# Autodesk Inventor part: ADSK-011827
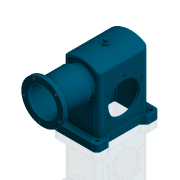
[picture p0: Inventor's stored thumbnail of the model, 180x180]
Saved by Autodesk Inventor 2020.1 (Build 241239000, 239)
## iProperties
Created: 2000-02
Part Number: ADSK-011827
Material: RA HRS
Document SubType Name: Modeling
Designer: glanglot
Density: 7.83 g/cm^3
Appearance: Bearing Blue
Mass: 18740 g
Surface Area: 5032.13 cm^2
Volume: 2393.35 cm^3
Control State: 0
Master: False
Checked Out: False
Shininess: 20.0
Length Units: 11269
Angle Units: 11279
Time Units: 11290
Mass Units: 11283
Length Display Precision: 3
Angle Display Precision: 2
Compacted: True
Dimensions: 178x291x377 mm
Mass: 18,74 kg
DocNumber: ADSK-011827_1.ipt
Folder: 01 - Themengebiete\Simplification\01 - Packaging machine\
VDS_Category: 3D Komponenten
VDS_NumSchm: Kein
Density: 0.0
Volumn: 0.0
Area: 0.0
PropertySet Name: Model Information
Title: A105195
Author: glanglot
Revision Number: -
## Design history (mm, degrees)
workaxis "Arbeitsachse3"
node "Extrusion1" dims "d2" = 0, "shaft_length_front" = 170
  sketch "Sketch1"
    geometry: C1 r 12.5 at (0, 0); 1 further point
    constraints: 1 centre point, 1 coincident
    dimensions: "d0" = 25 diameter of C1
sketch "Sketch2"
  geometry: L1 (-70, 76)-(70, 76); L2 (70, 76)-(70, -169); L3 (-70, -169)-(-70, 76); L4 (-70, -60.325)-(70, -60.325); L5 (-70, 52)-(70, 52); L6 (-89, -197)-(89, -197); L7 (89, -197)-(89, -169); L8 (89, -169)-(-89, -169); L9 (-89, -169)-(-89, -197); L10 (0, 76)-(0, -197); A1 r 114.083 centre (0, -38.083) between (70, 52) and (-70, 52); 1 further point
  constraints: 20 end point, 7 point on line, 4 parallel, 3 point on circle, 2 horizontal, 2 midpoint, 2 perpendicular, 1 centre point, 1 vertical
  dimensions: "d3" = 76 distance from line of point (0, 0) L1; "d6" = 140 distance between parallel lines of L2 L3; "d7" = 24 distance between parallel lines of L5 L1; "d8" = 178 distance between parallel lines of L7 L9; "d9" = 28 distance between parallel lines of L8 L6; "d10" = 197 distance from line of point (0, 0) L6
node "Extrusion2" dims "d11" = 200, "d12" = 0
node "Extrusion3" dims "d13" = 250, "d14" = 0
workaxis "Arbeitsachse4"
  workplane "Arbeitsebene8"
node "Extrusion4" dims "d18" = 0, "shaft_length_right_left" = 300
  sketch "Sketch3"
    geometry: L1 (-197, -125)-(-197, 125) reference; L2 (-197, 0)-(-77, 0); C1 r 19 at (-77, 0)
    constraints: 2 end point, 1 centre point, 1 coincident, 1 midpoint, 1 perpendicular
    dimensions: "d15" = 38 diameter of C1
node "Extrusion5" dims "d20" = 10, "d21" = 0
  sketch "Sketch4"
    geometry: C1 r 56.5 at (0, 0); C2 r 12.5 at (0, 0); 1 further point
    constraints: 2 centre point, 2 coincident
    dimensions: "d19" = 113 diameter of C1; "d199" = 25 diameter of C2
node "Extrusion6" dims "d37" = 7.493, "d38" = 0
  sketch "Sketch5"
    geometry: L1 (-124.6, 0)-(124.6, 0) reference; L2 (45, -15.911)-(45, 0); L3 (45, 0)-(58.557, -23.481); L4 (45, 0)-(34.815, -17.64); L5 (45, 0)-(16.133, 0); L6 (45, 0)-(76.079, 0); L7 (45, 0)-(29.151, 27.452); L8 (45, 0)-(45, 29.465); L9 (45, 0)-(64.626, 33.993); L10 (49.041, -7)-(40.959, -7); L11 (49.041, -7)-(53.083, 0); L12 (40.959, -7)-(36.917, 0); L13 (36.917, 0)-(40.959, 7); L14 (40.959, 7)-(49.041, 7); L15 (53.083, 0)-(49.041, 7); C1 r 12.5 at (0, 0) reference; 1 further point
    constraints: 28 end point, 7 point on line, 4 perpendicular, 3 collinear, 3 parallel, 1 coincident, 1 equal length, 3 other
    dimensions: "d33" = 7 distance between parallel lines of L10 L6; "d34" = 30 deg angle of L8 L7; "d35" = 30 deg angle of L9 L8 (= d34); "d36" = 45 distance of L2.end C1.centre
node "Circular Pattern1" dims "d39" = 60, "d41" = 60 deg
node "Extrusion7" dims "d43" = 9.525, "d44" = 0
  sketch "Sketch6"
    geometry: C1 r 88.9 at (100, -129); C2 r 19 at (100, -129)
    constraints: 2 centre point, 1 coincident
    dimensions: "d42" = 177.8 diameter of C1; "d197" = 38 diameter of C2
node "Extrusion8" dims "d49" = 7.493, "d50" = 0
  sketch "Sketch7"
    geometry: L1 (0, 0)-(202.768, 0); L2 (76, 0)-(76, 13.354); L3 (76, 0)-(67.315, 15.042); L4 (76, 0)-(81.961, 10.326); L5 (71.959, 7)-(80.041, 7); L6 (80.041, 7)-(84.083, 0); L7 (71.959, 7)-(67.917, 0); L8 (67.917, 0)-(71.959, -7); L9 (71.959, -7)-(80.041, -7); L10 (80.041, -7)-(84.083, 0); C1 r 88.9 at (0, 0) reference
    constraints: 20 end point, 5 parallel, 5 point on line, 2 equal length, 1 coincident, 1 horizontal, 1 perpendicular
    dimensions: "d45" = 7 distance between parallel lines of L1 L5; "d46" = 30 deg angle of L2 L3; "d47" = 30 deg angle of L4 L2; "d48" = 76 distance of L2.start L1.start
node "Circular Pattern2" dims "d51" = 60, "d53" = 60 deg
workplane "Work Plane3"
node "Extrusion12" dims "d70" = 5, "d71" = 0
  sketch "Sketch11"
    geometry: L1 (100, -5)-(150, -5); L2 (100, 5)-(150, 5); L3 (150, -5)-(150, 5); L4 (0, -7)-(0, 7) reference; L5 (197.8, 0)-(-136.8, 0) reference; A1 r 5 centre (100, 0) between (100, -5) and (100, 5); 1 further point
    constraints: 6 end point, 2 horizontal, 2 point on circle, 2 tangent, 1 centre point, 1 midpoint, 1 point on line, 1 vertical
    dimensions: "d68" = 10 diameter of A1; "d200" = 150 distance between parallel lines of L3 L4 (derived); "d201" = 50 distance of L1.start L1.end
node "Extrusion15" dims "d135" = 5, "d136" = 0
  sketch "Sketch18"
    geometry: L1 (-100, 5)-(-150, 5); L2 (-100, -5)-(-150, -5); L3 (-150, -5)-(-150, 5); L4 (136.8, 0)-(-197.8, 0) reference; L5 (0, -7)-(0, 7) reference; A1 r 5 centre (-100, 0) between (-100, 5) and (-100, -5); 1 further point
    constraints: 6 end point, 2 point on circle, 2 point on line, 2 tangent, 1 centre point, 1 horizontal, 1 midpoint, 1 vertical
    dimensions: "d133" = 10 diameter of A1; "d202" = 50 distance of L2.start L2.end; "d203" = 150 distance between parallel lines of L3 L5 (derived)
node "Mirror1"
workplane "Work Plane1"
node "Extrusion9" dims "d56" = 6, "d57" = 0
  sketch "Sketch8"
    geometry: C1 r 12.5 at (0, 0); 1 further point
    constraints: 1 centre point, 1 coincident
    dimensions: "d55" = 25 diameter of C1
node "Extrusion10" dims "d60" = 12, "d61" = 0
  sketch "Sketch9"
    geometry: L1 (-6, 6)-(6, 6); L2 (6, 6)-(6, -6); L3 (6, -6)-(-6, -6); L4 (-6, -6)-(-6, 6); L5 (0, 6)-(0, -6); L6 (6, 0)-(-6, 0); C1 r 12.5 at (0, 0) reference
    constraints: 12 end point, 6 midpoint, 2 parallel, 1 horizontal, 1 perpendicular
    dimensions: "d58" = 12 distance between parallel lines of L2 L4; "d59" = 12 distance between parallel lines of L3 L1 (= d58)
workplane "Work Plane2"
node "Extrusion11" dims "d65" = 3.5814, "d66" = 0
  sketch "Sketch10"
    geometry: L1 (3, 125)-(3, 170); L2 (-3, 125)-(-3, 170); L3 (3, 170)-(-3, 170); L4 (0, -184)-(0, 229) reference; L5 (-124.6, 0)-(124.6, 0) reference; A1 r 3 centre (0, 125) between (3, 125) and (-3, 125); 1 further point
    constraints: 6 end point, 2 point on circle, 2 tangent, 2 vertical, 1 centre point, 1 horizontal, 1 midpoint, 1 point on line
    dimensions: "d64" = 6 diameter of A1; "d204" = 170 distance between parallel lines of L5 L3 (derived); "d205" = 45 distance of L2.start L2.end
node "Chamfer1" dims "d137" = 0.8, "d138" = 0.8, "d180" = 45 deg
node "Hole1" dims "d80" = 13.5, "d81" = 9.525, "d82" = 6.35, "d83" = 60 deg, "d84" = 19.05, "d85" = 118 deg, "d198" = 6
  sketch "Sketch12"
    geometry: L1 (17.5, -231.5)-(160.5, -231.5); L2 (160.5, -231.5)-(160.5, -18.5); L3 (160.5, -18.5)-(17.5, -18.5); L4 (17.5, -18.5)-(17.5, -231.5); L5 (0, -250)-(0, 0) reference; L6 (0, -250)-(178, -250) reference; 6 further points
    constraints: 8 end point, 4 midpoint, 2 coincident, 2 parallel, 1 horizontal, 1 horizontal alignment, 1 perpendicular, 1 vertical alignment
    dimensions: "d181" = 143 distance of L2.end L3.end; "d182" = 213 distance of L3.end L1.start
node "Mirror2"
node "Extrusion13" dims "d94" = 25.4, "d95" = 0
  sketch "Sketch14"
    geometry: L1 (19, 224.919)-(19, 25.081) reference; L2 (19.32, 225)-(158.68, 225) reference; L3 (28.678, 225)-(19, 215.322); C1 r 12.5 at (17.5, 231.5); C2 r 12.5 at (160.5, 231.5); C3 r 12.5 at (160.5, 18.5); C4 r 12.5 at (17.5, 18.5); A1 r 6.75 centre (17.5, 18.5) between (19, 25.081) and (19.32, 25) reference; A2 r 6.75 centre (160.5, 231.5) between (159, 224.919) and (158.68, 225) reference; A3 r 6.75 centre (160.5, 18.5) between (158.68, 25) and (159, 25.081) reference; A4 r 16.521 centre (35.521, 208.479) between (35.521, 225) and (19, 208.479); A5 r 6.75 centre (17.5, 231.5) between (19, 224.919) and (19.32, 225) reference
    constraints: 5 centre point, 4 point on line, 4 tangent, 3 coincident, 3 equal radius, 2 end point, 2 point on circle, 1 concentric
    dimensions: "d92" = 45 deg angle of L2 L3; "d96" = 25 diameter of C1
node "Mirror3"
node "Mirror4"
node "Extrusion14" dims "d129" = 28 (= d9), "d130" = 0
  sketch "Sketch17"
    geometry: L1 (0, -250)-(0, 0) reference; L2 (178, -250)-(178, 0) reference; L3 (18, -186.5)-(18, -63.5); L4 (160, -63.5)-(160, -186.5); L5 (160, -63.5)-(178, -45.5); L6 (18, -63.5)-(0, -45.5); L7 (18, -186.5)-(0, -204.5); L8 (160, -186.5)-(178, -204.5); L9 (160, -125)-(18, -125); L10 (89, 50)-(89, -300) reference; 2 further points
    constraints: 14 end point, 5 midpoint, 4 point on line, 3 equal length, 3 horizontal alignment, 1 vertical
    dimensions: "d183" = 18 distance between parallel lines of L1 L3; "d184" = 123 distance of L3.start L3.end; "d185" = 45 deg angle of L1 L7
node "Fillet3" dims "d131" = 17.5
node "Fillet4" dims "d132" = 6
node "Revolution1" dims "d110" = 90 deg
  sketch "Sketch15"
    geometry: L1 (0, 282.4)-(0, 69.6) reference; L2 (84, 252)-(84, 238); L3 (84, 238)-(63.5, 238); L4 (63.5, 238)-(63.5, 125.5); L5 (63.5, 125.5)-(56, 118); L6 (84, 252)-(57, 252); L7 (57.5, 242.887)-(57.5, 144); L8 (55.5, 128)-(0, 128); L9 (-219.6, 0)-(134.6, 0) reference; L10 (57.5, 242.887)-(57, 242.887); L11 (55.5, 128)-(55.5, 139.374); L12 (57, 252)-(57, 242.887); L13 (-169, 100)-(62.689, 100) reference; L14 (56, 118)-(56, 100); L15 (56, 100)-(0, 100); L16 (0, 100)-(0, 128); A1 r 6.35 centre (51.15, 144) between (55.5, 139.374) and (57.5, 144); 1 further point
    constraints: 26 end point, 6 perpendicular, 6 point on line, 2 parallel, 2 point on circle, 1 centre point, 1 tangent, 1 vertical
    dimensions: "d97" = 84 distance between parallel lines of L1 L2; "d98" = 63.5 distance between parallel lines of L1 L4; "d101" = 14 distance between parallel lines of L3 L6; "d104" = 242.8875 distance between parallel lines of L9 L10; "d105" = 12.7 diameter of A1; "d106" = 6 distance between parallel lines of L4 L7; "d107" = 55.5 distance between parallel lines of L1 L11; "d108" = 16 distance from line of A1.centre L8; "d109" = 57 distance between parallel lines of L12 L1; "d188" = 56 distance between parallel lines of L1 L14; "d189" = 124 distance between parallel lines of L6 L8; "d190" = 45 deg angle of L4 L5; "d191" = 18 distance of L5.end L14.end; "d192" = 28 distance between parallel lines of L13 L8
node "Fillet1" dims "d111" = 3
node "Fillet2" dims "d112" = 5
node "Hole2" dims "d116" = 8.376, "d117" = 9.525, "d118" = 6.35, "d119" = 60 deg, "d120" = 27.3, "d121" = 118 deg, "d193" = 20
  sketch "Sketch16"
    geometry: L1 (0, 152.2)-(0, -255.2) reference; L2 (-53.033, -53.033)-(53.033, 53.033); C1 r 84 at (0, 0) reference; C2 r 57 at (0, 0) reference; A1 r 75 centre (0, 0) between (53.033, 53.033) and (-53.033, -53.033)
    constraints: 2 end point, 2 point on circle, 1 centre point, 1 coincident, 1 midpoint
    dimensions: "d113" = 150 diameter of A1; "d114" = 45 deg angle of L2 L1 (= d115)
node "Fillet5" dims "d141" = 6
node "Fillet6" dims "d142" = 6
workaxis "Work Axis1"
workplane "Work Plane4"
workplane "Work Plane5"
node "Extrusion18" dims "d150" = 25.4, "d151" = 0
  sketch "Sketch21"
    geometry: L1 (89, -169)-(89, -197) reference; L2 (89, -197)-(-89, -197) reference; L3 (-89, -197)-(-89, -169) reference; L4 (-89, -169)-(-66.498, -169) reference; L5 (-66.498, -169)-(-66.498, 50.61) reference; L6 (66.498, 50.61)-(66.498, -169) reference; L7 (66.498, -169)-(89, -169) reference; L8 (-59.146, 50.223)-(-59.146, 49.901); L9 (59.146, -197)-(59.146, 49.901); L10 (-59.146, 49.901)-(-59.146, -197); L11 (59.146, 49.901)-(59.146, 50.223); L12 (59.146, -197)-(-59.146, -197); A1 r 114.083 centre (0, -38.083) between (59.288, 59.384) and (-59.288, 59.384) reference; A2 r 106.017 centre (0, -38.083) between (59.146, 49.901) and (-59.146, 49.901)
    constraints: 12 end point, 2 point on circle, 2 point on line, 1 centre point, 1 collinear, 2 other
node "Fillet7" dims "d152" = 6, "d195" = 6
node "Extrusion19" dims "d154" = 25.4, "d155" = 0
  sketch "Sketch22"
    geometry: C1 r 88.9 at (85.82, 92.71) reference; C2 r 19 at (85.82, 92.71)
    constraints: 1 centre point, 1 coincident
    dimensions: "d179" = 38 diameter of C2
node "Extrusion20" dims "d156" = 25.4, "d157" = 0
  sketch "Sketch23"
    geometry: C1 r 4.763 at (85.82, 168.91) reference
node "Circular Pattern3" dims "d158" = 60, "d160" = 360 deg
node "Extrusion21" dims "d162" = 25.4, "d163" = 0
node "Fillet8" dims "d164" = 6.35
node "Fillet10" dims "d166" = 3.175
workaxis "Work Axis2"
node "Extrusion22" dims "d168" = 50, "d169" = 0
  sketch "Sketch25"
    geometry: L1 (-414.522, 196.85)-(113.278, 196.85) reference; C1 r 7.5 at (-111.736, 196.85)
    constraints: 1 centre point, 1 point on line
    dimensions: "d167" = 15 diameter of C1
node "Extrusion23" dims "d171" = 25, "d172" = 0
  sketch "Sketch26"
    geometry: C1 r 16 at (-111.736, 196.85); C2 r 7.5 at (-111.736, 196.85) reference; 1 further point
    constraints: 1 centre point, 1 coincident
    dimensions: "d170" = 32 diameter of C1
node "Fillet11" dims "d173" = 3.175
workplane "Work Plane6"
workplane "Work Plane7"
node "Circular Pattern4" dims "d176" = 50, "d178" = 360 deg
node "Extrusion17" dims "d144" = 25.4, "d145" = 0
node "Solide1"
node "Corps solides"
node "Corps surfaciques"
sketch "Sketch20"
  geometry: C1 r 88.9 at (85.82, 92.71) reference; C2 r 63.5 at (85.82, 92.71)
  constraints: 1 centre point, 1 coincident
  dimensions: "d143" = 127 diameter of C2
sketch "Sketch24"
  geometry: C1 r 55.5 at (0, 0) reference; C2 r 9.906 at (0, 0)
  constraints: 1 centre point, 1 coincident
  dimensions: "d161" = 19.812 diameter of C2
node "Schnittkanten projizieren2"
other parameters: "d54" = 76 (= d3), "d62" = 12.5 (= 0.5 x d0), "d67" = -57.15, "d115" = 45 deg, "d146" = -6.35, "d149" = -6.35, "d174" = 0, "d175" = 90 deg
